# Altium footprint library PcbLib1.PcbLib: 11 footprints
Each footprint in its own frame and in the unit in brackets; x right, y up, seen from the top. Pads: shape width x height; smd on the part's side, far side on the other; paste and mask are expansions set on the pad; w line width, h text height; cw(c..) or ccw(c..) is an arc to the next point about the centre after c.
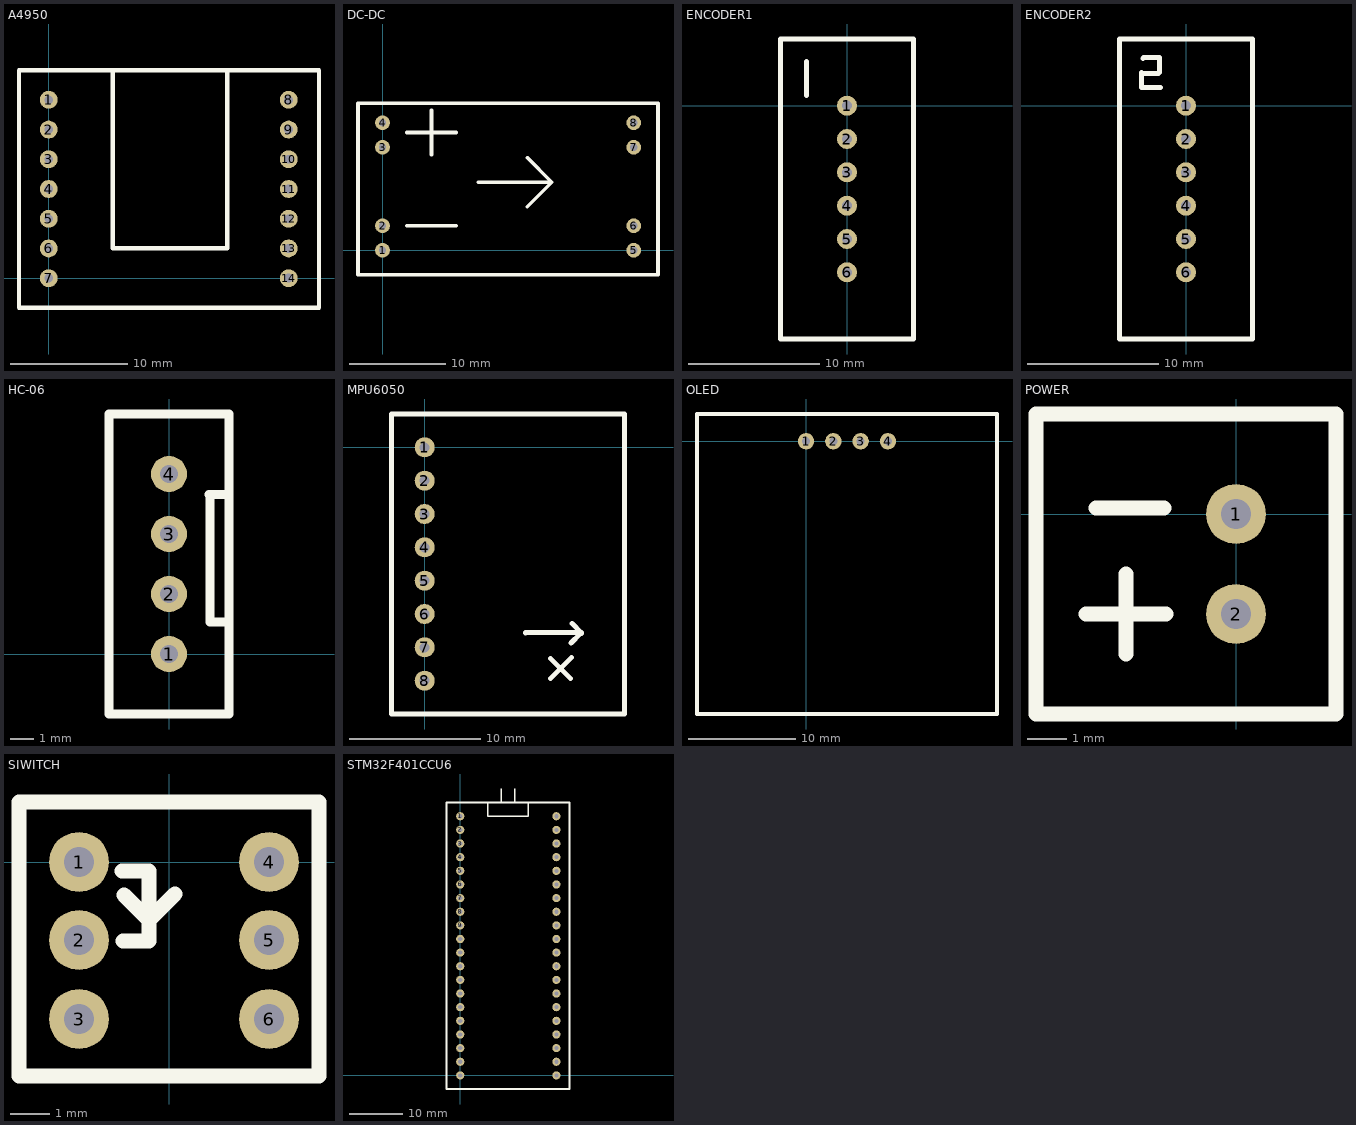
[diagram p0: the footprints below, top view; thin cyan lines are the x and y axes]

## A4950 [mil]
pads (14):
  round 60 hole 30: 1(0,600) 2(0,500) 3(0,400) 4(0,300) 5(0,200) 6(0,100) 7(0,0) 8(807,600) 9(807,500) 10(807,400) 11(807,300) 12(807,200) 13(807,100) 14(807,0)
Top Overlay:
  lines w15: 215,700 215,100 600,100 600,700 ; -100,-100 -100,700 909,700 909,-100 -100,-100

## DC-DC [mil]
pads (8):
  round 60 hole 30: 1(0,0) 2(0,100) 3(0,420) 4(0,520) 5(1024,0) 6(1024,100) 7(1024,420) 8(1024,520)
Top Overlay:
  lines w15: 100,100 300,100 ; 100,480 300,480 ; 200,390 200,410 200,550 200,570 ; 390,278 690,278 ; 590,178 690,278 ; 590,378 690,278 ; -100,-100 1123,-100 1123,323 1123,600 -100,600 -100,-100

## ENCODER1 [mil]
pads (6):
  round 60 hole 30: 1(0,0) 2(0,-100) 3(0,-200) 4(0,-300) 5(0,-400) 6(0,-500)
Top Overlay:
  lines w15: -122,31 -122,132 ; -200,-700 -200,200 200,200 200,-700 -200,-700

## ENCODER2 [mil]
pads (6):
  round 60 hole 30: 1(0,0) 2(0,-100) 3(0,-200) 4(0,-300) 5(0,-400) 6(0,-500)
Top Overlay:
  lines w15: -129,142 -127,144 -80,144 -80,99 -83,96 -131,96 -134,99 -133,98 -133,55 -132,54 -77,54 ; -200,-700 200,-700 200,200 -200,200 -200,-700

## HC-06 [mil]
pads (4):
  round 60 hole 30: 1(0,0) 2(0,100) 3(0,200) 4(0,300)
Top Overlay:
  lines w15: 94,53 68,53 68,265 67,266 97,266 97,267 ; -100,-100 100,-100 100,400 -100,400 -100,-100

## MPU6050 [mil]
pads (8):
  round 60 hole 30: 1(0,0) 2(0,-100) 3(0,-200) 4(0,-300) 5(0,-400) 6(0,-500) 7(0,-600) 8(0,-700)
Top Overlay:
  lines w15: 302,-557 302,-556 467,-556 ; 378,-693 440,-631 ; 378,-633 378,-634 437,-693 ; 439,-587 467,-559 467,-556 ; 442,-528 470,-556 470,-559 467,-556 ; -100,-800 600,-800 600,100 -100,100 -100,-700 -100,-800

## OLED [mil]
pads (4):
  round 60 hole 30: 1(0,0) 2(100,0) 3(200,0) 4(300,0)
Top Overlay:
  lines w15: -200,100 -400,100 ; -400,100 -400,-1000 -300,-1000 700,-1000 700,100 -400,100

## PIN_HEADER [mil]

## POWER [mil]
pads (2):
  round 60 hole 30: 1(0,0) 2(0,-100)
Top Overlay:
  lines w15: -150,-100 -70,-100 ; -140,6 -72,6 ; -110,-140 -110,-60 ; -200,-200 100,-200 100,100 -200,100 -200,-200

## SIWITCH [mil]
pads (6):
  round 60 hole 30: 1(-90,0) 2(-90,-78) 3(-90,-157) 4(100,0) 5(100,-78) 6(100,-157)
Top Overlay:
  lines w15: -90,60 90,60 150,60 ; -47,-9 -20,-9 -20,-79 -46,-79 ; -45,-33 -20,-58 6,-32 ; 150,60 150,-214 -150,-214 -150,60 -120,60 150,60

## STM32F401CCU6 [mil]
pads (40):
  round 60 hole 30: 1(0,1900) 2(0,1800) 3(0,1700) 4(0,1600) 5(0,1500) 6(0,1400) 7(0,1300) 8(0,1200) 9(0,1100) 10(0,1000) 11(0,900) 12(0,800) 13(0,700) 14(0,600) 15(0,500) 16(0,400) 17(0,300) 18(0,200) 19(0,100) 20(0,0) 21(705,1900) 22(705,1800) 23(705,1700) 24(705,1600) 25(705,1500) 26(705,1400) 27(705,1300) 28(705,1200) 29(705,1100) 30(705,1000) 31(705,900) 32(705,800) 33(705,700) 34(705,600) 35(705,500) 36(705,400) 37(705,300) 38(705,200) 39(705,100) 40(705,0)
Top Overlay:
  lines w10: 200,2000 200,1900 500,1900 500,2000 ; 300,2000 300,2100 ; 400,2000 400,2100
  lines w15: -100,-100 800,-100 800,1900 800,2000 -100,2000 -100,0 -100,-100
